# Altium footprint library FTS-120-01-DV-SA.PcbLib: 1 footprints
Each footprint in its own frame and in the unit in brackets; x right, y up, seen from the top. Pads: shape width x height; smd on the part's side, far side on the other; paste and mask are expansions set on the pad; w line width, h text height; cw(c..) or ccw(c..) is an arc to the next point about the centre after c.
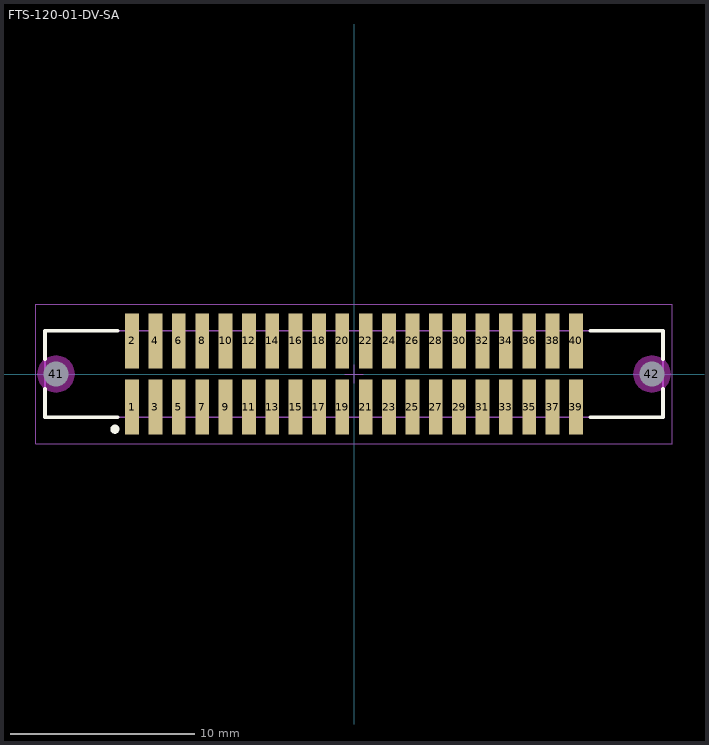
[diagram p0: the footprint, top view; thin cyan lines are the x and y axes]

## FTS-120-01-DV-SA [mm] "1.27mm pitch, 40 pin, micro strip; shrouded, w/alignment pins"
height 4.32
pads (42):
  rect 0.75x3 smd mask+0: 1(-12.065,-1.8) 2(-12.065,1.8) 3(-10.795,-1.8) 4(-10.795,1.8) 5(-9.525,-1.8) 6(-9.525,1.8) 7(-8.255,-1.8) 8(-8.255,1.8) 9(-6.985,-1.8) 10(-6.985,1.8) 11(-5.715,-1.8) 12(-5.715,1.8) 13(-4.445,-1.8) 14(-4.445,1.8) 15(-3.175,-1.8) 16(-3.175,1.8) 17(-1.905,-1.8) 18(-1.905,1.8) 19(-0.635,-1.8) 20(-0.635,1.8) 21(0.635,-1.8) 22(0.635,1.8) 23(1.905,-1.8) 24(1.905,1.8) 25(3.175,-1.8) 26(3.175,1.8) 27(4.445,-1.8) 28(4.445,1.8) 29(5.715,-1.8) 30(5.715,1.8) 31(6.985,-1.8) 32(6.985,1.8) 33(8.255,-1.8) 34(8.255,1.8) 35(9.525,-1.8) 36(9.525,1.8) 37(10.795,-1.8) 38(10.795,1.8) 39(12.065,-1.8) 40(12.065,1.8)
  round 1 hole 1.35 unplated mask+0: 41(-16.2,0) 42(16.2,0)
Top Overlay:
  circle w0.25: c-13,-3 r0.125
  lines w0.2: -16.8,-0.8 -16.8,-2.35 -12.85,-2.35 ; -16.8,0.8 -16.8,2.35 -12.85,2.35 ; 12.85,-2.35 16.8,-2.35 16.8,-0.8 ; 12.85,2.35 16.8,2.35 16.8,0.8
Keep-Out Layer:
  pour cut-out: 17.209,0 17.174,0.261 17.073,0.504 16.913,0.713 16.704,0.873 16.461,0.974 16.2,1.009 15.939,0.974 15.696,0.873 15.487,0.713 15.327,0.504 15.226,0.261 15.191,0 15.226,-0.261 15.327,-0.504 15.487,-0.713 15.696,-0.873 15.939,-0.974 16.2,-1.009 16.461,-0.974 16.704,-0.873 16.913,-0.713 17.073,-0.504 17.174,-0.261
  pour cut-out: -15.191,0 -15.226,0.261 -15.327,0.504 -15.487,0.713 -15.696,0.873 -15.939,0.974 -16.2,1.009 -16.461,0.974 -16.704,0.873 -16.913,0.713 -17.073,0.504 -17.174,0.261 -17.209,0 -17.174,-0.261 -17.073,-0.504 -16.913,-0.713 -16.704,-0.873 -16.461,-0.974 -16.2,-1.009 -15.939,-0.974 -15.696,-0.873 -15.487,-0.713 -15.327,-0.504 -15.226,-0.261
Mechanical 12:
  lines w0.001: -16.8,-2.35 -16.8,2.35 16.8,2.35 16.8,-2.35 -16.8,-2.35
Mechanical 13:
  lines w0.1: -16.8,-2.35 -16.8,2.35 16.8,2.35 16.8,-2.35 -16.8,-2.35
  text ".Designator" at 0.254,0.254 h1.52
Mechanical 15:
  lines w0.05: -0.5,0 0.5,0 ; 0,-0.5 0,0.5 ; -17.3,-3.8 -17.3,3.8 17.3,3.8 17.3,-3.8 -17.3,-3.8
